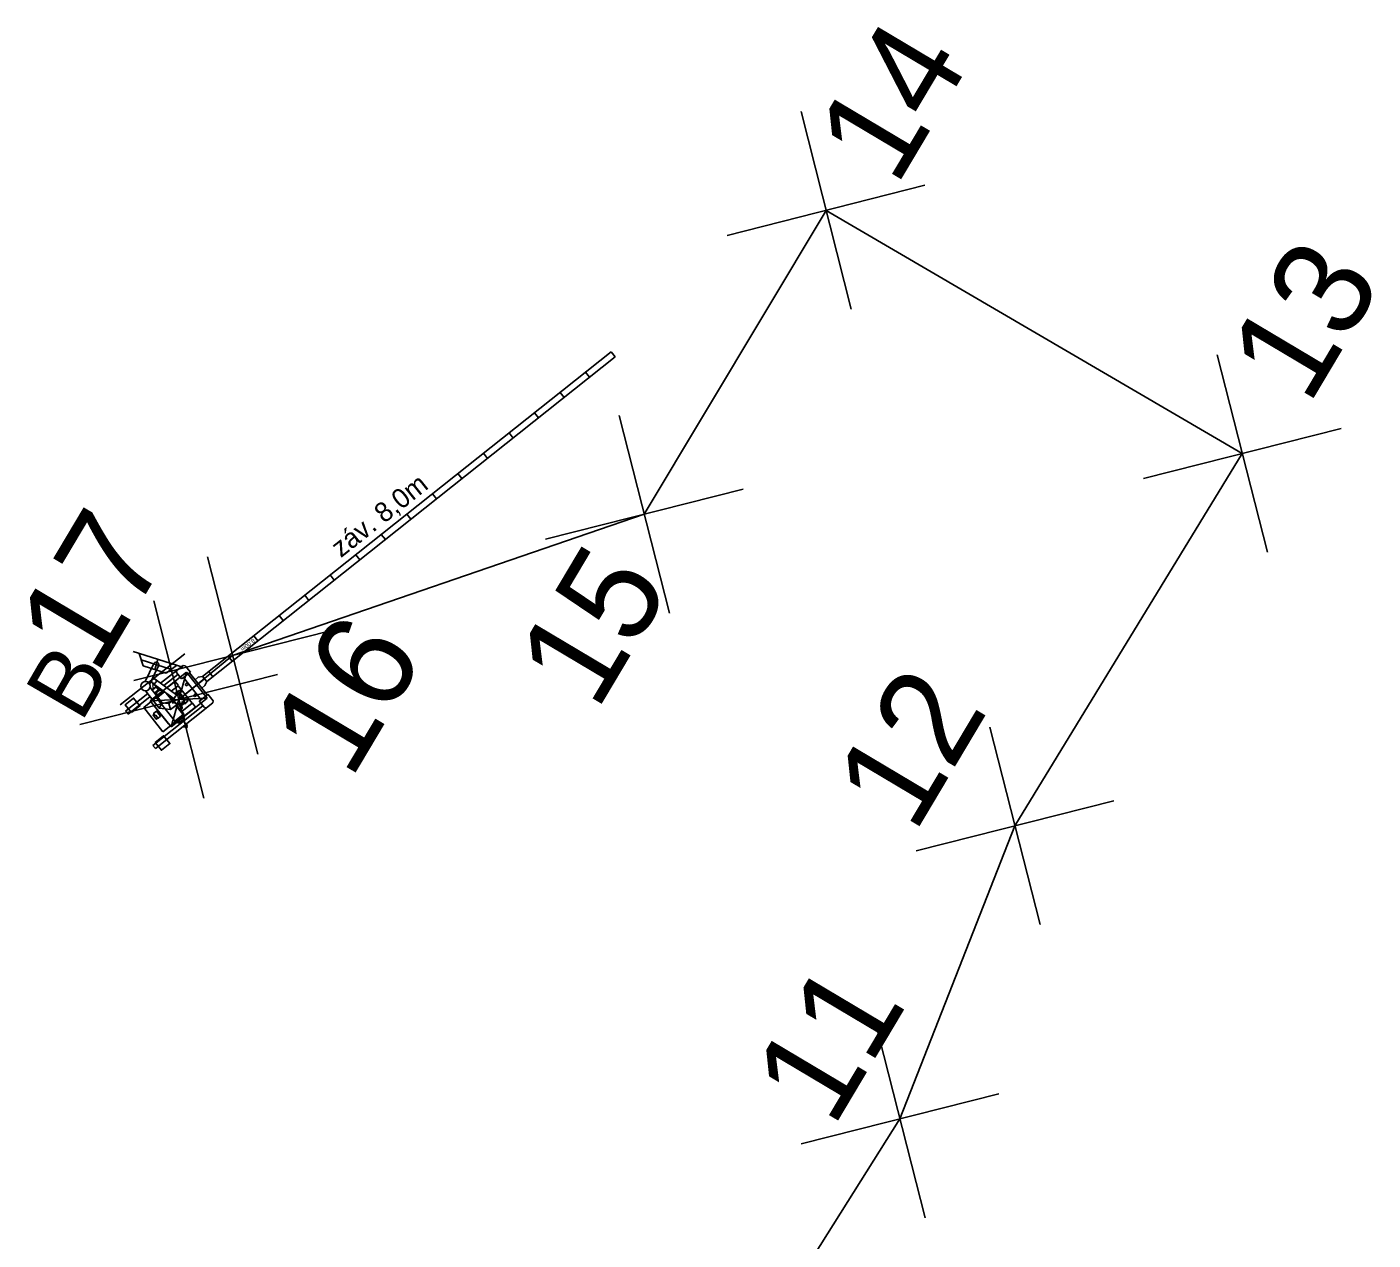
# Model space of a CAD drawing. Extents: x -553584 to -553445, y -1067272 to -1066959.
# Drawn here: x -553577.52 to -553556.88, y -1067222.01 to -1067203.41 of the extents above; entities that cross this region are included whole.
import ezdxf

# ---------------------------------------------------------------- set-up
doc = ezdxf.new("R2010")
doc.units = 0
for name, color, linetype in [('Body', 7, 'Continuous'), ('Default', 7, 'Continuous'), ('Křížky', 7, 'Continuous'), ('Nová kabelizace', 7, 'Continuous'), ('nové prvky ZZ', 7, 'Continuous')]:
    doc.layers.add(name, color=color, linetype=linetype)

# ---------------------------------------------------------------- blocks, each defined once
blk = doc.blocks.new('Křížek')
at = {"layer": 'Křížky'}
for p, q in [((8.84, -8.84), (-8.84, 8.84)), ((8.84, -8.84), (-8.84, 8.84)), ((8.84, -8.84), (-8.84, 8.84)), ((8.84, 8.84), (-8.84, -8.84))]:
    blk.add_line(p, q, dxfattribs=at)

msp = doc.modelspace()

# ---------------------------------------------------------------- linework, layer by layer
at = {"layer": 'Nová kabelizace'}
msp.add_line((-553568.058, -1067210.885), (-553565.27, -1067206.226), dxfattribs=at)
for points in [[(-553558.888, -1067209.954), (-553565.27, -1067206.226)], [(-553558.888, -1067209.954), (-553562.374, -1067215.662), (-553564.137, -1067220.156)], [(-553575.196, -1067213.726), (-553574.37, -1067213.051), (-553568.058, -1067210.885)], [(-553564.043, -1067230.581), (-553564.846, -1067228.027), (-553566.884, -1067224.575), (-553566.87, -1067224.492), (-553564.137, -1067220.156)]]:
    msp.add_lwpolyline(points, dxfattribs=at)
at = {"layer": 'nové prvky ZZ'}
for p, q in [((-553574.83, -1067213.372), (-553568.566, -1067208.395)), ((-553568.566, -1067208.395), (-553568.504, -1067208.473)), ((-553574.768, -1067213.449), (-553568.504, -1067208.473)), ((-553568.958, -1067208.706), (-553568.896, -1067208.784)), ((-553569.349, -1067209.017), (-553569.287, -1067209.095)), ((-553569.741, -1067209.328), (-553569.679, -1067209.406)), ((-553570.132, -1067209.639), (-553570.07, -1067209.717)), ((-553570.524, -1067209.95), (-553570.462, -1067210.028)), ((-553570.915, -1067210.261), (-553570.853, -1067210.339)), ((-553571.307, -1067210.572), (-553571.245, -1067210.65)), ((-553571.698, -1067210.883), (-553571.636, -1067210.961)), ((-553572.09, -1067211.194), (-553572.028, -1067211.272)), ((-553572.481, -1067211.505), (-553572.419, -1067211.583)), ((-553572.872, -1067211.816), (-553572.811, -1067211.894)), ((-553573.264, -1067212.127), (-553573.202, -1067212.205)), ((-553573.655, -1067212.438), (-553573.594, -1067212.516)), ((-553574.047, -1067212.75), (-553573.985, -1067212.827)), ((-553576.092, -1067213.809), (-553575.105, -1067213.025)), ((-553575.896, -1067212.99), (-553575.133, -1067213.232)), ((-553575.801, -1067213.021), (-553575.74, -1067213.211)), ((-553575.771, -1067213.116), (-553575.308, -1067213.263)), ((-553575.578, -1067213.173), (-553575.713, -1067213.45)), ((-553575.515, -1067213.111), (-553575.564, -1067213.267)), ((-553575.533, -1067213.195), (-553575.546, -1067213.184)), ((-553575.545, -1067213.196), (-553575.534, -1067213.183)), ((-553574.438, -1067213.061), (-553574.377, -1067213.138)), ((-553575.74, -1067213.211), (-553575.388, -1067213.323)), ((-553575.506, -1067213.207), (-553575.641, -1067213.486)), ((-553575.077, -1067213.305), (-553575.632, -1067213.748)), ((-553575.128, -1067213.202), (-553575.474, -1067213.477)), ((-553575.208, -1067213.341), (-553575.425, -1067213.513)), ((-553575.229, -1067213.202), (-553575.388, -1067213.323)), ((-553575.315, -1067214.146), (-553575.077, -1067213.305)), ((-553575.23, -1067213.313), (-553575.227, -1067213.281)), ((-553575.152, -1067213.411), (-553575.23, -1067213.313)), ((-553575.125, -1067213.39), (-553575.152, -1067213.411)), ((-553575.096, -1067213.207), (-553575.128, -1067213.202)), ((-553575.018, -1067213.305), (-553575.096, -1067213.207)), ((-553574.759, -1067213.704), (-553575.077, -1067213.305)), ((-553575.032, -1067213.316), (-553575.018, -1067213.305)), ((-553574.83, -1067213.372), (-553574.768, -1067213.449)), ((-553574.675, -1067213.376), (-553574.737, -1067213.298)), ((-553575.706, -1067213.593), (-553575.494, -1067213.859)), ((-553575.448, -1067213.777), (-553575.636, -1067213.54)), ((-553575.53, -1067213.522), (-553575.604, -1067213.58)), ((-553575.599, -1067213.513), (-553575.579, -1067213.497)), ((-553575.599, -1067213.513), (-553575.594, -1067213.518)), ((-553575.594, -1067213.518), (-553575.598, -1067213.521)), ((-553575.598, -1067213.521), (-553575.59, -1067213.531)), ((-553575.597, -1067213.473), (-553575.268, -1067213.717)), ((-553575.579, -1067213.497), (-553575.574, -1067213.503)), ((-553575.574, -1067213.503), (-553575.571, -1067213.5)), ((-553575.571, -1067213.5), (-553575.563, -1067213.51)), ((-553575.481, -1067213.558), (-553575.567, -1067213.626)), ((-553575.557, -1067213.416), (-553575.227, -1067213.66)), ((-553575.537, -1067213.541), (-553575.552, -1067213.539)), ((-553575.53, -1067213.547), (-553575.537, -1067213.541)), ((-553575.505, -1067213.577), (-553575.53, -1067213.547)), ((-553575.494, -1067213.659), (-553575.422, -1067213.602)), ((-553575.423, -1067213.603), (-553575.436, -1067213.601)), ((-553575.252, -1067213.449), (-553575.377, -1067213.549)), ((-553575.207, -1067213.514), (-553575.312, -1067213.597)), ((-553575.252, -1067213.449), (-553575.206, -1067213.507)), ((-553575.206, -1067213.507), (-553575.21, -1067213.51)), ((-553575.21, -1067213.51), (-553575.207, -1067213.514)), ((-553574.993, -1067213.783), (-553575.207, -1067213.514)), ((-553575.196, -1067213.726), (-553574.799, -1067213.41)), ((-553574.946, -1067213.423), (-553574.843, -1067213.553)), ((-553575.672, -1067213.635), (-553576.011, -1067213.904)), ((-553575.636, -1067213.681), (-553575.974, -1067213.95)), ((-553574.759, -1067213.704), (-553575.632, -1067213.748)), ((-553575.351, -1067214.1), (-553575.632, -1067213.748)), ((-553575.314, -1067214.147), (-553575.632, -1067213.748)), ((-553574.672, -1067213.776), (-553575.555, -1067214.477)), ((-553575.516, -1067213.691), (-553575.413, -1067213.609)), ((-553575.494, -1067213.859), (-553575.448, -1067213.777)), ((-553575.448, -1067213.777), (-553575.346, -1067213.787)), ((-553575.294, -1067213.746), (-553575.39, -1067213.627)), ((-553575.286, -1067213.738), (-553575.354, -1067213.653)), ((-553575.346, -1067213.787), (-553575.29, -1067213.743)), ((-553575.322, -1067213.88), (-553575.346, -1067213.787)), ((-553575.322, -1067213.88), (-553575.222, -1067213.801)), ((-553574.759, -1067213.704), (-553575.315, -1067214.146)), ((-553575.301, -1067213.756), (-553575.285, -1067213.737)), ((-553575.284, -1067213.768), (-553575.301, -1067213.756)), ((-553575.285, -1067213.737), (-553575.27, -1067213.748)), ((-553575.284, -1067213.738), (-553575.268, -1067213.726)), ((-553575.237, -1067213.794), (-553575.273, -1067213.768)), ((-553575.255, -1067213.768), (-553575.266, -1067213.759)), ((-553575.24, -1067213.65), (-553575.223, -1067213.637)), ((-553575.124, -1067213.942), (-553575.231, -1067213.808)), ((-553575.23, -1067213.658), (-553575.216, -1067213.646)), ((-553575.199, -1067213.616), (-553575.214, -1067213.636)), ((-553575.214, -1067213.636), (-553575.195, -1067213.649)), ((-553575.192, -1067213.723), (-553575.2, -1067213.729)), ((-553575.181, -1067213.63), (-553575.199, -1067213.616)), ((-553575.199, -1067213.722), (-553575.193, -1067213.73)), ((-553575.172, -1067213.657), (-553575.184, -1067213.649)), ((-553575.144, -1067213.665), (-553575.177, -1067213.64)), ((-553575.171, -1067213.815), (-553575.117, -1067213.772)), ((-553575.145, -1067213.839), (-553575.167, -1067213.812)), ((-553575.16, -1067213.821), (-553575.109, -1067213.781)), ((-553574.993, -1067213.783), (-553575.151, -1067213.909)), ((-553574.99, -1067213.787), (-553574.993, -1067213.783)), ((-553574.986, -1067213.784), (-553574.99, -1067213.787)), ((-553574.94, -1067213.842), (-553574.986, -1067213.784)), ((-553574.854, -1067213.73), (-553574.882, -1067213.752)), ((-553574.882, -1067213.752), (-553574.803, -1067213.85)), ((-553574.761, -1067213.656), (-553574.748, -1067213.645)), ((-553574.748, -1067213.645), (-553574.669, -1067213.744)), ((-553574.669, -1067213.744), (-553574.672, -1067213.776)), ((-553575.974, -1067213.95), (-553576.011, -1067213.904)), ((-553574.826, -1067213.822), (-553575.592, -1067214.431)), ((-553575.516, -1067214.01), (-553575.514, -1067214.012)), ((-553575.494, -1067213.859), (-553575.322, -1067213.88)), ((-553575.255, -1067214.059), (-553575.133, -1067213.962)), ((-553575.246, -1067214.07), (-553575.127, -1067213.975)), ((-553575.134, -1067213.949), (-553575.24, -1067213.815)), ((-553575.178, -1067213.875), (-553575.152, -1067213.854)), ((-553575.155, -1067213.845), (-553575.172, -1067213.824)), ((-553575.171, -1067213.884), (-553575.149, -1067213.867)), ((-553575.152, -1067213.854), (-553575.155, -1067213.845)), ((-553575.149, -1067213.867), (-553575.144, -1067213.858)), ((-553575.143, -1067213.848), (-553575.145, -1067213.839)), ((-553575.144, -1067213.858), (-553575.143, -1067213.848)), ((-553575.133, -1067213.962), (-553575.134, -1067213.949)), ((-553575.127, -1067213.99), (-553574.94, -1067213.842)), ((-553575.127, -1067213.975), (-553575.119, -1067213.959)), ((-553575.119, -1067213.959), (-553575.124, -1067213.942)), ((-553574.803, -1067213.85), (-553574.771, -1067213.855)), ((-553575.181, -1067214.071), (-553575.13, -1067214.03)), ((-553575.123, -1067214.059), (-553575.099, -1067214.089)), ((-553575.099, -1067214.089), (-553575.095, -1067214.098)), ((-553575.089, -1067214.161), (-553575.097, -1067214.151)), ((-553575.095, -1067214.098), (-553575.096, -1067214.113)), ((-553575.086, -1067214.158), (-553575.089, -1067214.161)), ((-553575.081, -1067214.164), (-553575.086, -1067214.158)), ((-553575.081, -1067214.164), (-553575.061, -1067214.148)), ((-553575.062, -1067214.14), (-553575.07, -1067214.13)), ((-553575.066, -1067214.142), (-553575.062, -1067214.14)), ((-553575.061, -1067214.148), (-553575.066, -1067214.142)), ((-553575.592, -1067214.431), (-553575.555, -1067214.477))]:
    msp.add_line(p, q, dxfattribs=at)
for points in [[(-553574.854, -1067213.73), (-553574.761, -1067213.656), (-553575.032, -1067213.316), (-553575.125, -1067213.39)], [(-553575.171, -1067213.61), (-553575.159, -1067213.6), (-553575.173, -1067213.582), (-553575.186, -1067213.592)], [(-553575.92, -1067213.926), (-553575.791, -1067213.824), (-553575.888, -1067213.703), (-553576.016, -1067213.805)], [(-553575.438, -1067214.222), (-553575.246, -1067214.07), (-553575.542, -1067213.697), (-553575.734, -1067213.85)], [(-553575.176, -1067213.823), (-553575.182, -1067213.828), (-553575.194, -1067213.814), (-553575.187, -1067213.809)], [(-553575.064, -1067213.745), (-553575.052, -1067213.735), (-553575.066, -1067213.717), (-553575.079, -1067213.727)], [(-553575.228, -1067214.077), (-553575.188, -1067214.045), (-553575.198, -1067214.031), (-553575.239, -1067214.063)], [(-553575.181, -1067214.104), (-553575.096, -1067214.037), (-553575.105, -1067214.026), (-553575.19, -1067214.093)], [(-553575.557, -1067214.383), (-553575.428, -1067214.281), (-553575.332, -1067214.402), (-553575.461, -1067214.504)]]:
    msp.add_lwpolyline(points, close=True, dxfattribs=at)
for points in [[(-553574.83, -1067213.372), (-553574.898, -1067213.383), (-553574.947, -1067213.422)], [(-553575.581, -1067213.549), (-553575.593, -1067213.534), (-553575.59, -1067213.531)], [(-553575.535, -1067213.518), (-553575.532, -1067213.523), (-553575.584, -1067213.564), (-553575.59, -1067213.556), (-553575.581, -1067213.549)], [(-553575.563, -1067213.51), (-553575.56, -1067213.507), (-553575.547, -1067213.522)], [(-553575.472, -1067213.565), (-553575.556, -1067213.632), (-553575.563, -1067213.623), (-553575.481, -1067213.558)], [(-553575.547, -1067213.522), (-553575.539, -1067213.516)], [(-553575.528, -1067213.633), (-553575.54, -1067213.619), (-553575.488, -1067213.578), (-553575.477, -1067213.593)], [(-553575.453, -1067213.58), (-553575.435, -1067213.601), (-553575.499, -1067213.652)], [(-553575.477, -1067213.593), (-553575.457, -1067213.577)], [(-553575.174, -1067213.623), (-553575.166, -1067213.617), (-553575.191, -1067213.586), (-553575.228, -1067213.615)], [(-553575.078, -1067213.51), (-553575.084, -1067213.515), (-553575.096, -1067213.5), (-553575.09, -1067213.495)], [(-553575.09, -1067213.495), (-553575.093, -1067213.491), (-553575.063, -1067213.467), (-553575.045, -1067213.49), (-553575.075, -1067213.514), (-553575.078, -1067213.51)], [(-553574.768, -1067213.449), (-553574.795, -1067213.513), (-553574.844, -1067213.552)], [(-553575.549, -1067213.65), (-553575.528, -1067213.633)], [(-553575.534, -1067213.669), (-553575.505, -1067213.646), (-553575.494, -1067213.659), (-553575.523, -1067213.682)], [(-553575.263, -1067213.754), (-553575.282, -1067213.78), (-553575.29, -1067213.775), (-553575.266, -1067213.744)], [(-553575.213, -1067213.635), (-553575.234, -1067213.607), (-553575.242, -1067213.614), (-553575.209, -1067213.655)], [(-553575.198, -1067213.653), (-553575.21, -1067213.638)], [(-553575.188, -1067213.654), (-553575.168, -1067213.628), (-553575.175, -1067213.622), (-553575.199, -1067213.653)], [(-553575.187, -1067213.805), (-553575.189, -1067213.807), (-553575.172, -1067213.828), (-553575.165, -1067213.822), (-553575.18, -1067213.804)], [(-553575.125, -1067213.761), (-553575.099, -1067213.794), (-553575.091, -1067213.788), (-553575.12, -1067213.751), (-553575.121, -1067213.752)], [(-553575.121, -1067213.751), (-553575.096, -1067213.782), (-553575.059, -1067213.752), (-553575.084, -1067213.72), (-553575.12, -1067213.748)], [(-553574.947, -1067213.674), (-553574.954, -1067213.68), (-553574.966, -1067213.665), (-553574.959, -1067213.659)], [(-553574.959, -1067213.659), (-553574.962, -1067213.655), (-553574.932, -1067213.632), (-553574.914, -1067213.655), (-553574.944, -1067213.678), (-553574.947, -1067213.674)], [(-553575.565, -1067213.979), (-553575.583, -1067213.957), (-553575.593, -1067213.964), (-553575.575, -1067213.987)], [(-553575.514, -1067214.012), (-553575.475, -1067213.98), (-553575.537, -1067213.902), (-553575.581, -1067213.938), (-553575.555, -1067213.971)], [(-553575.575, -1067213.987), (-553575.541, -1067214.029), (-553575.516, -1067214.01), (-553575.55, -1067213.967), (-553575.565, -1067213.979)], [(-553575.13, -1067214.03), (-553575.109, -1067214.013), (-553575.13, -1067213.986), (-553575.194, -1067214.037)], [(-553575.217, -1067214.068), (-553575.202, -1067214.087), (-553575.181, -1067214.071)], [(-553575.181, -1067214.071), (-553575.173, -1067214.08), (-553575.122, -1067214.04), (-553575.13, -1067214.03)], [(-553575.079, -1067214.112), (-553575.07, -1067214.104), (-553575.076, -1067214.096), (-553575.128, -1067214.138), (-553575.122, -1067214.146), (-553575.113, -1067214.139)], [(-553575.113, -1067214.139), (-553575.1, -1067214.154), (-553575.097, -1067214.151)], [(-553575.07, -1067214.13), (-553575.067, -1067214.127), (-553575.079, -1067214.112)]]:
    msp.add_lwpolyline(points, dxfattribs=at)
for centre, radius in [((-553575.539, -1067213.189), 0.00856), ((-553575.705, -1067213.521), 0.0716), ((-553575.577, -1067213.444), 0.0347), ((-553575.196, -1067213.726), 0.0725)]:
    msp.add_circle(centre, radius, dxfattribs=at)
for centre, radius, start, end in [((-553575.542, -1067213.191), 0.0399, 332.4445, 154.1515), ((-553575.196, -1067213.726), 0.0795, 238.9157, 49.4497)]:
    msp.add_arc(centre, radius, start, end, dxfattribs=at)

# ---------------------------------------------------------------- block references
at = {"layer": 'Body', "xscale": 0.12500000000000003, "yscale": 0.125, "rotation": 59.23917986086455}
for p in [(-553565.27, -1067206.226), (-553558.888, -1067209.954), (-553568.058, -1067210.885), (-553574.37, -1067213.051), (-553575.196, -1067213.726), (-553562.374, -1067215.662), (-553564.137, -1067220.156)]:
    msp.add_blockref('Křížek', p, dxfattribs=at)

# ---------------------------------------------------------------- texts
at = {"layer": 'Default'}
for s, p in [('14', (-553564.197, -1067205.88)), ('13', (-553557.873, -1067209.235)), ('17', (-553576.455, -1067213.376)), ('15', (-553568.789, -1067213.923)), ('16', (-553572.562, -1067214.976)), ('12', (-553563.916, -1067215.799)), ('11', (-553565.164, -1067220.312))]:
    msp.add_text(s, height=1.5, rotation=59.2392, dxfattribs=at).set_placement(p)
at = {"layer": 'nové prvky ZZ'}
for s, height, rotation, p in [('záv. 8,0m', 0.3, 38.4684, (-553572.71, -1067211.56)), ('B', 1.025, 59.9447, (-553576.694, -1067214.097)), ('B', 1.025, 59.9447, (-553576.694, -1067214.097)), ('8,00m', 0.0646, 218.4684, (-553574.06, -1067212.786)), ('265', 0.025, 218.4684, (-553575.159, -1067213.738))]:
    msp.add_text(s, height=height, rotation=rotation, dxfattribs=at).set_placement(p)

doc.saveas('drawing.dxf')
